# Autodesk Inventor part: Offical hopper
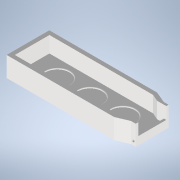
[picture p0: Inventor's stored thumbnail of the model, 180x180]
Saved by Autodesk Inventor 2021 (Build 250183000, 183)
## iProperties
Created: 2020-08
Part Number: Offical hopper
Material: Steel, High Strength, Low Alloy
Document SubType Name: Modeling
Designer: karim
Density: 7.85 g/cm^3
Appearance: Steel - Polished
Mass: 4540.06 g
Surface Area: 1311.87 cm^2
Volume: 578.352 cm^3
Author: karim
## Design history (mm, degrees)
sketch "Sketch1"
  geometry: L1 (150, -50)-(150, 50); L2 (150, 50)-(-150, -50); L3 (-150, 50)-(150, -50); L4 (160, -60)-(160, 60); L5 (-160, 42.444)-(-160, -42.443); L6 (150, -50)-(-77.565, -50); L7 (-150.512, 35)-(-150.512, -35); L8 (-77.565, -50)-(-150.512, -35); L9 (150, 50)-(-77.565, 50); L10 (-77.565, 50)-(-150.512, 35); L11 (160, 0)-(-160, 0); L12 (160, 60)-(-114.038, 60); L13 (-114.038, 60)-(-160, 42.444); L14 (160, -60)-(-114.038, -60); L15 (-114.038, -60)-(-160, -42.443); 1 further point
  constraints: 30 end point, 4 horizontal, 4 midpoint, 2 vertical, 1 perpendicular
  dimensions: "d0" = 100 distance of L3.start L2.end; "d1" = 300 distance of L2.end L1.start; "d2" = 10 distance between parallel lines of L1 L4; "d7" = 84.887 distance of L5.start L5.end; "d8" = 70 distance of L7.start L7.end; "d13" = 310 distance between parallel lines of L1 L5
extrude "Extrusion1" new body sketch "Sketch1" distance "d3" = 10; taper "d4" = 0 deg
extrude "Extrusion2" join sketch "Sketch1" distance "d5" = 50; taper "d6" = 0 deg
sketch "Sketch2"
  geometry: L1 (-144.188, -46.433)-(-144.188, 42.767); L2 (-144.188, 42.767)-(114.861, 42.767); L3 (114.861, 42.767)-(149.483, 21.995); L4 (149.483, 21.995)-(149.483, -27.29); L5 (149.483, -27.29)-(114.861, -43.582); L6 (114.861, -43.582)-(-144.188, -46.433); 1 further point
  constraints: 12 end point, 1 parallel, 1 perpendicular, 1 vertical
extrude "Extrusion3" cut sketch "Sketch2" distance "d15" = 40; taper "d16" = 0 deg
sketch "Sketch3"
  geometry: L1 (-144.188, 42.767)-(114.861, 42.767) reference; L2 (114.038, 60)-(-160, 60) reference; L3 (-160, 60)-(114.861, 60); L4 (114.861, 60)-(114.861, 52.767); L5 (114.861, 52.767)-(-160, 52.767); L6 (-160, 52.767)-(-160, 60); 2 further points
  constraints: 8 end point, 2 parallel, 1 horizontal, 1 perpendicular
  dimensions: "d17" = 10 distance of L4.end L1.end
extrude "Extrusion4" cut sketch "Sketch3" distance "d18" = 50; taper "d19" = 0 deg
sketch "Sketch4"
  geometry: L1 (114.861, -43.582)-(-144.188, -46.433) reference; L2 (114.861, -43.582)-(-144.188, -43.582); L3 (-144.188, -43.582)-(-144.188, -46.433); L4 (-144.188, -46.433)-(114.861, -46.433); L5 (114.861, -46.433)-(114.861, -43.582); 1 further point
  constraints: 8 end point, 2 parallel, 1 horizontal, 1 perpendicular
extrude "Extrusion5" join sketch "Sketch4" distance "d20" = 50; taper "d21" = 0 deg
sketch "Sketch5"
  geometry: L1 (114.038, -53.773)-(-160, -53.773); L2 (-160, -60)-(114.038, -60) reference; L3 (-160, -53.773)-(114.038, -53.773); L4 (114.038, -53.773)-(114.038, -60); L5 (114.038, -60)-(-160, -60); L6 (-160, -60)-(-160, -53.773); 3 further points
  constraints: 10 end point, 2 parallel, 1 horizontal, 1 perpendicular
extrude "Extrusion6" cut sketch "Sketch5" distance "d23" = 50; taper "d24" = 0 deg
sketch "Sketch6"
  geometry: L1 (114.861, 42.767)-(149.483, 21.995) reference; L2 (149.483, 27.29)-(114.861, 42.767); L3 (114.861, 42.767)-(149.483, 21.995); L4 (149.483, 27.29)-(149.483, 21.995); 1 further point
  constraints: 6 end point, 1 vertical
extrude "Extrusion7" cut sketch "Sketch6" distance "d26" = 40; taper "d27" = 0 deg
sketch "Sketch7"
  geometry: L1 (114.038, -53.773)-(160, -34.353); L2 (160, -42.444)-(160, 42.443) reference; L3 (114.038, -60)-(160, -42.444) reference; L4 (-160, -53.773)-(114.038, -53.773) reference; L5 (114.038, -53.773)-(114.038, -60) reference; L6 (114.038, -53.773)-(114.038, -60); L7 (114.038, -60)-(160, -42.444); L8 (160, -34.353)-(160, -42.444); 1 further point
  constraints: 8 end point, 1 collinear, 1 point on line, 1 vertical
  dimensions: "d28" = 2 deg angle of L1 L3
extrude "Extrusion8" cut sketch "Sketch7" distance "d29" = 50; taper "d30" = 0 deg
sketch "Sketch8"
  geometry: L1 (114.861, 59.686)-(114.861, 52.767) reference; L2 (114.861, 52.767)-(160, 33.695); L3 (160, -34.353)-(160, 42.443) reference; L4 (160, 42.443)-(114.861, 59.686) reference; L5 (114.861, 52.767)-(114.861, 59.686); L6 (114.861, 59.686)-(160, 42.443); L7 (160, 33.695)-(160, 42.443); 1 further point
  constraints: 8 end point, 3 collinear, 1 point on line
  dimensions: "d31" = 2 deg angle of L4 L2
extrude "Extrusion9" cut sketch "Sketch8" distance "d32" = 50; taper "d33" = 0 deg
sketch "Sketch9"
  geometry: L1 (61.643, 50)-(61.643, 10) reference; L2 (7.063, 20)-(61.643, 20); L3 (61.643, 20)-(61.643, 50); L4 (61.643, 50)-(7.063, 50); L5 (7.063, 50)-(7.063, 20); 2 further points
  constraints: 8 end point, 2 parallel, 1 horizontal, 1 perpendicular
  dimensions: "d34" = 30 distance of L4.end L2.start
extrude "Extrusion10" cut sketch "Sketch9" distance "d35" = 50; taper "d36" = 0 deg
sketch "Sketch10"
  geometry: L1 (-160, -53.773)-(114.038, -53.773) reference; L2 (-160, 52.767)-(-154.508, 52.767); L3 (-154.508, 52.767)-(-154.508, -53.773); L4 (-154.508, -53.773)-(-160, -53.773); L5 (-160, -53.773)-(-160, 52.767); 2 further points
  constraints: 8 end point, 2 parallel, 1 horizontal, 1 perpendicular, 1 point on line
extrude "Extrusion11" cut sketch "Sketch10" distance "d39" = 50; taper "d40" = 0 deg
sketch "Sketch11"
  geometry: C1 r 30 at (-81.751, 0); C2 r 30 at (81.751, 0); C3 r 30 at (0, 0); 1 further point
  constraints: 3 centre point, 1 coincident
  dimensions: "d41" = 60 diameter of C1; "d43" = 60 diameter of C2; "d46" = 60 diameter of C3
extrude "Extrusion12" cut sketch "Sketch11" distance "d47" = 3; taper "d48" = 0 deg
sketch "Sketch12"
  geometry: L1 (149.483, -27.34)-(149.483, 27.336) reference; L2 (149.483, -27.29)-(114.861, -43.582) reference; L3 (133.14, 35.02)-(133.14, -34.98); L4 (160, -34.98)-(160, 35.02); L5 (133.14, -34.98)-(160, -34.98); L6 (133.14, 35.02)-(160, 35.02); 2 further points
  constraints: 8 end point, 1 horizontal, 1 parallel, 1 point on line
extrude "Extrusion13" cut sketch "Sketch12" distance "d53" = 30; taper "d54" = 0 deg
sketch "Sketch13"
  geometry: L1 (-10.517, 7.063)-(-45.139, -9.229) reference; L2 (-26.818, -0.608)-(-10.517, 7.063); L3 (-10.517, 7.063)-(-10.517, -0.628); L4 (-1.486, -0.628)-(-26.86, -0.628) reference; L5 (-26.86, -0.628)-(-26.818, -0.608); L6 (-26.86, -0.628)-(-10.517, -0.628); 1 further point
  constraints: 8 end point, 3 point on line, 2 collinear, 1 perpendicular, 1 vertical
extrude "Extrusion14" cut sketch "Sketch13" distance "d55" = 10; taper "d56" = 0 deg
sketch "Sketch14"
  geometry: L1 (133.14, 34.596)-(133.14, 35.02) reference; L2 (133.14, 35.02)-(133.14, 34.596); L3 (133.14, 34.596)-(132.172, 35.029); L4 (114.861, 42.767)-(149.483, 27.29) reference; L5 (133.14, 35.02)-(132.172, 35.029); 1 further point
  constraints: 6 end point, 1 collinear, 1 midpoint
extrude "Extrusion15" cut sketch "Sketch14" distance "d57" = 30; taper "d58" = 0 deg
sketch "Sketch15"
  geometry: L1 (-10.517, -0.628)-(-10.517, 61.643) reference; L2 (-10.517, 61.643)-(-10.517, 69.372); L3 (-26.86, 69.372)-(-3.136, 69.372) reference; L4 (-10.517, 61.643)-(-27.828, 69.381) reference; L5 (-10.517, 69.372)-(-27.828, 69.381); L6 (-27.828, 69.381)-(-10.517, 61.643); 1 further point
  constraints: 6 end point, 1 point on line, 1 vertical
extrude "Extrusion16" cut sketch "Sketch15" distance "d59" = 10; taper "d60" = 0 deg
node "Sketch16"
sketch "Sketch17"
  geometry: L1 (160, -34.353)-(114.038, -53.773) reference; L2 (155.367, -36.31)-(164.504, -36.31); L3 (164.504, -36.31)-(164.504, 35.954); L4 (164.504, 35.954)-(155.367, 35.954); L5 (155.367, 35.954)-(155.367, -36.31); 1 further point
  constraints: 8 end point, 2 parallel, 1 horizontal, 1 perpendicular, 1 point on line
extrude "Extrusion17" cut sketch "Sketch17" distance "d62" = 50; taper "d63" = 0 deg
sketch "Sketch18"
  geometry: L1 (155.367, -36.31)-(155.367, -34.98) reference; L2 (155.367, -36.31)-(155.367, -41.31); L3 (155.367, -41.31)-(143.533, -41.31); L4 (155.367, -36.31)-(114.038, -53.773) reference; L5 (143.533, -41.31)-(155.367, -36.31); L6 (155.367, 35.652)-(155.367, 40.652); L7 (155.367, 40.652)-(143.533, 40.652); L8 (155.367, 35.652)-(114.861, 52.767) reference; L9 (143.533, 40.652)-(155.367, 35.652); 1 further point
  constraints: 12 end point, 2 point on line, 2 vertical, 1 collinear, 1 horizontal, 1 perpendicular
  dimensions: "d64" = 5 distance of L1.start L2.end; "d65" = 5 distance of L6.start L6.end
extrude "Extrusion18" join sketch "Sketch18" distance "d66" = 50; taper "d67" = 0 deg
sketch "Sketch25"
  geometry: 1 further point
sketch "Sketch27"
  geometry: 2 further points
hole "Hole5" sketch "Sketch27" at (6.112, -39.869) diameter "d118" = 6.35; stored, may be unused: countersink angle "d122" = 90 deg, drill point angle "d124" = 118 deg; dims "d119" = 6, "d120" = 4, "d121" = 2, "d123" = 90
fillet "Fillet4" dims "d125" = 2
fillet "Fillet5" dims "d126" = 2
fillet "Fillet6" dims "d127" = 2
fillet "Fillet7" dims "d128" = 2
body "Solid1"
